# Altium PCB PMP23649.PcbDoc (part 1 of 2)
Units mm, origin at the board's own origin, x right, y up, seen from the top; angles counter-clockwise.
Board outline 75 x 70 mm, 2 copper layers (Top Layer, Bottom Layer), stack 1.575 mm thick; 49 components, 23 nets, 125 pads, 45 vias.
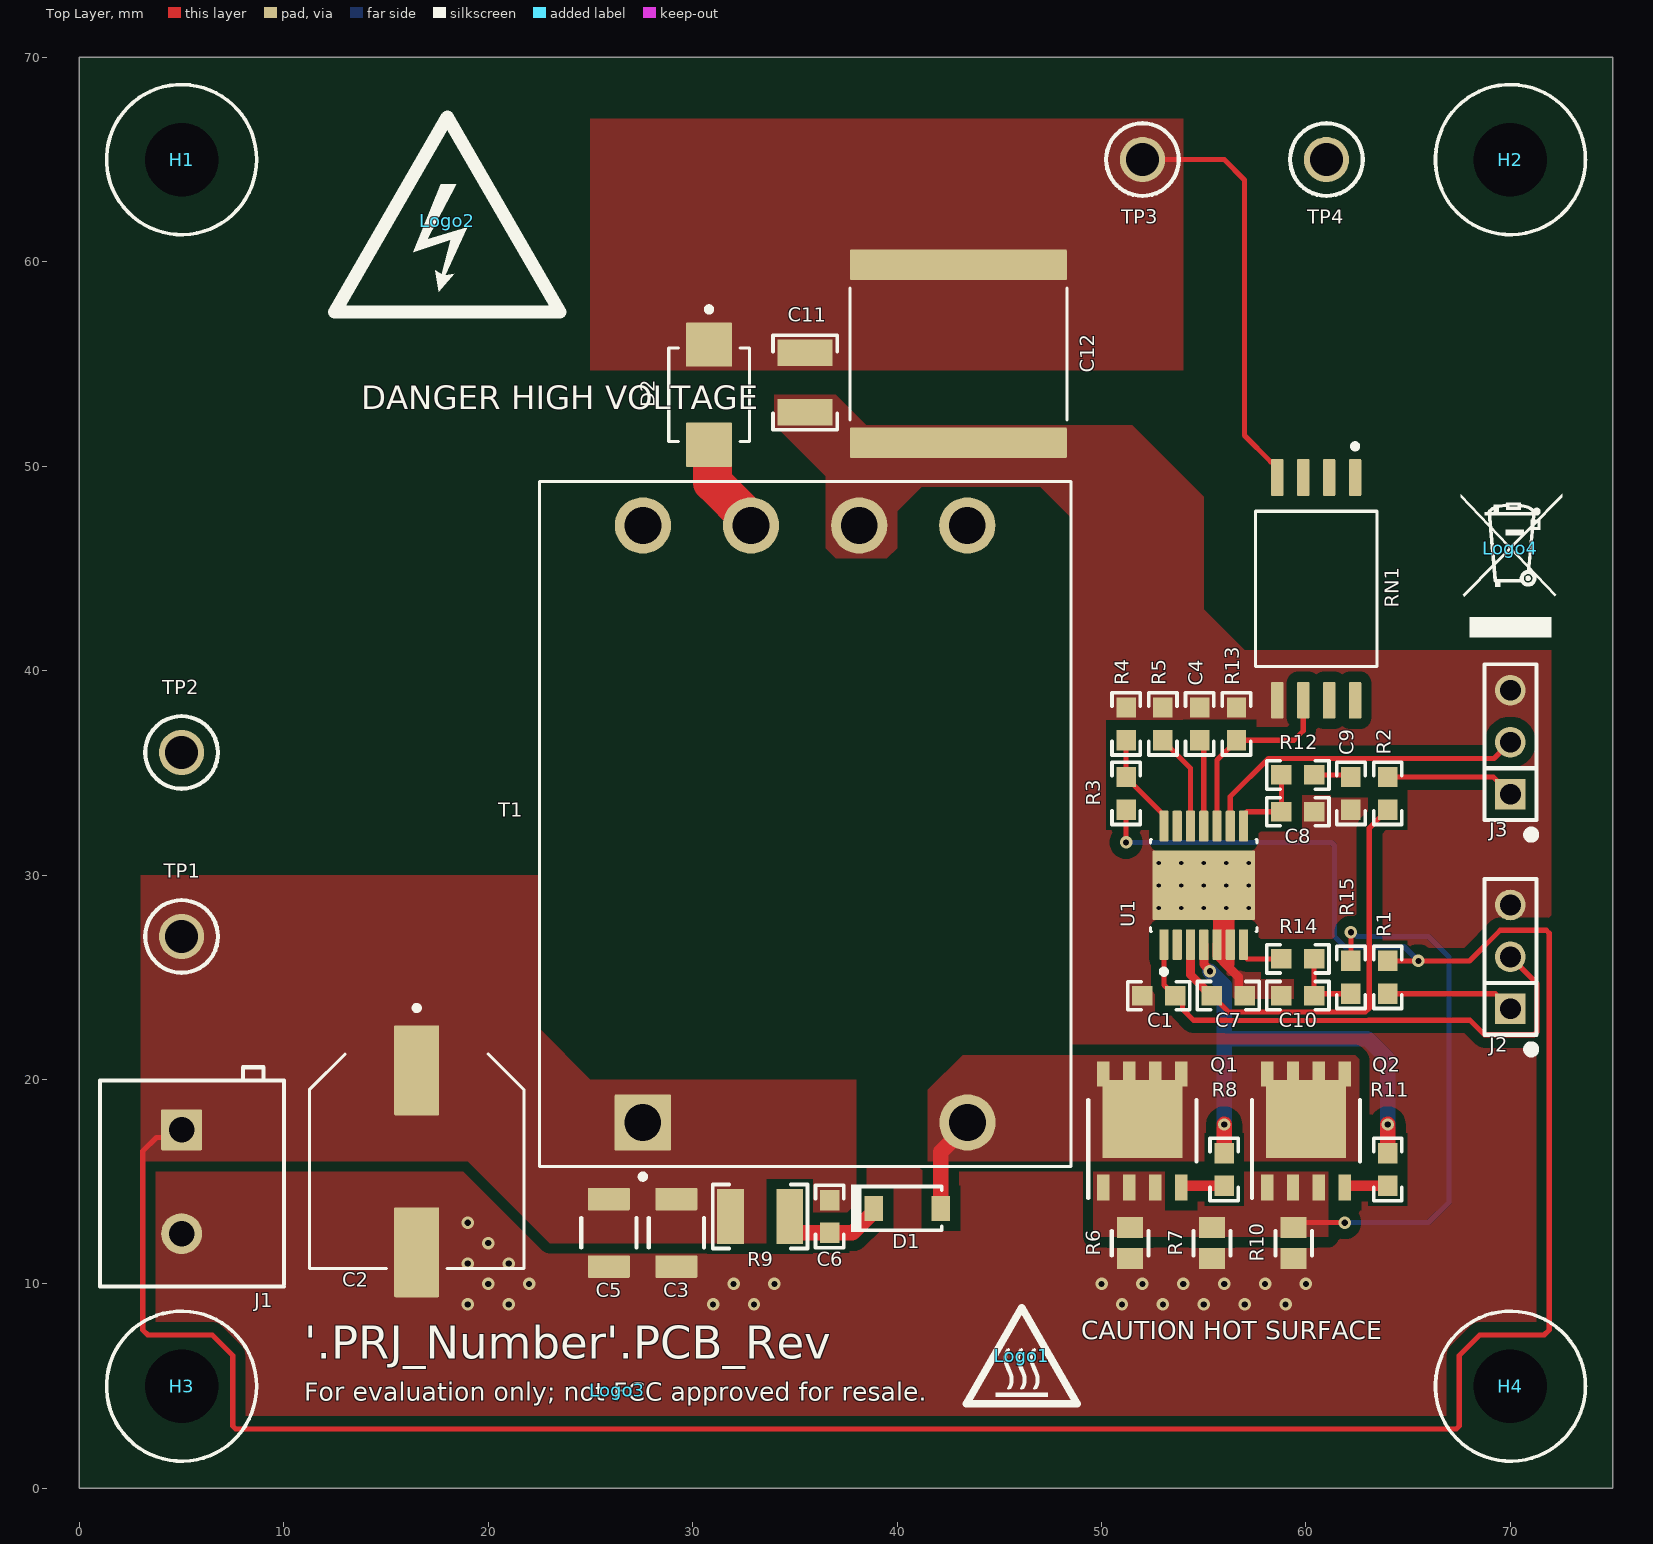
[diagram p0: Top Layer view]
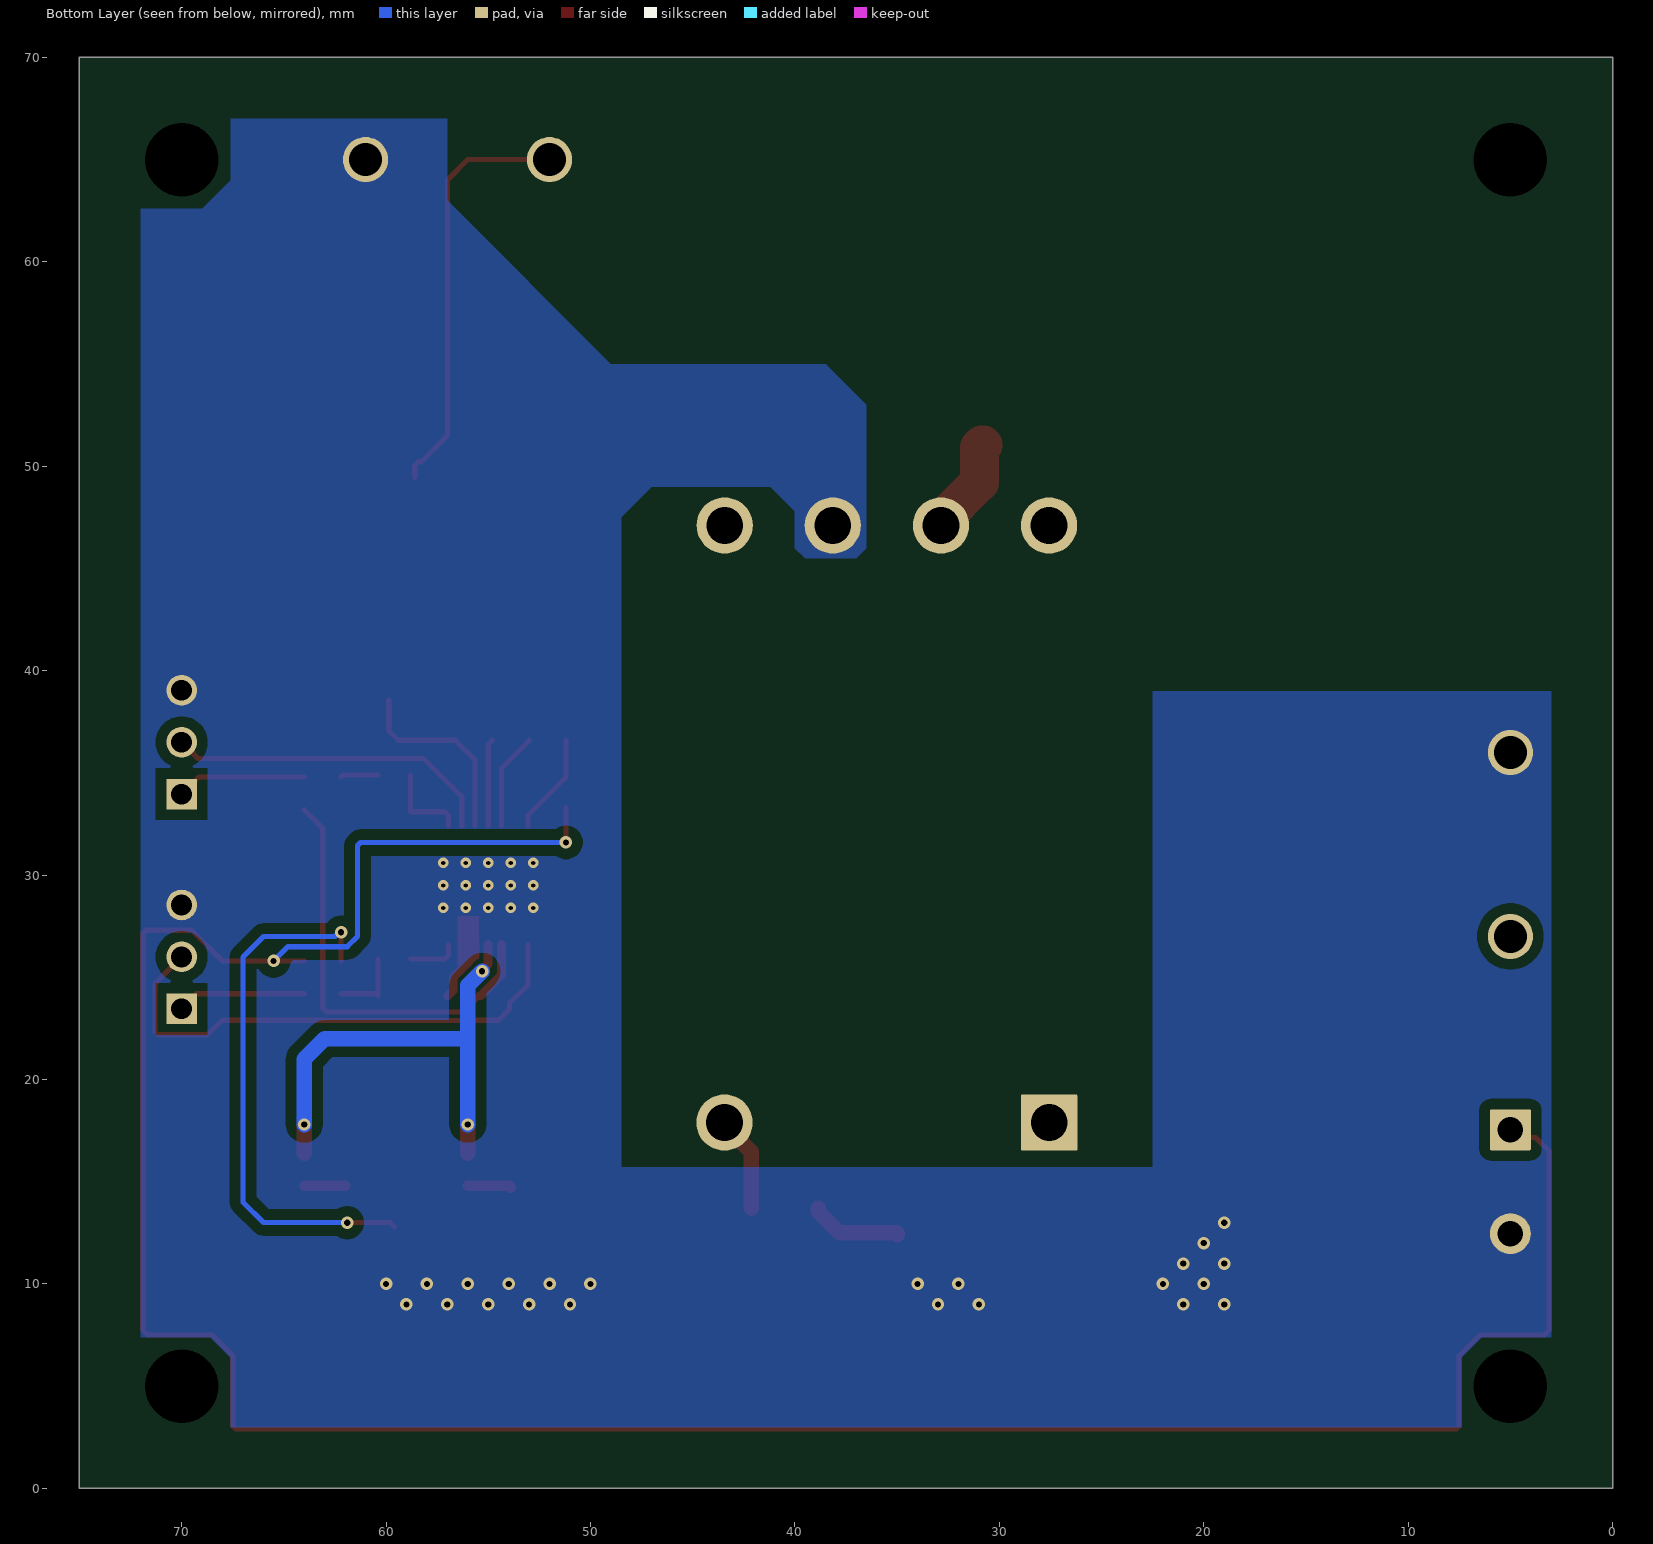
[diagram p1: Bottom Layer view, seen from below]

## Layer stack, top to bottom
Top Solder: solder mask 0.0102, Solder Resist, Dk 3.5
Top Layer: signal copper 0.0356
Dielectric1: core 1.5037, FR-4 High Tg, Dk 4.8
Bottom Layer: signal copper 0.0356
Bottom Solder: solder mask 0.0102, Solder Resist, Dk 3.5

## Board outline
0,0 0,70 75,70 75,0

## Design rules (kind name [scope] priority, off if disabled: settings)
AcuteAngle [All] p1: minimum=4.50000000000000E+0001 checktracksonly=FALSE
AssemblyTestPointUsage [All] p1: valid=2
BoardOutlineClearance BoardOutlineClearance_MountingHoles [OnCopper and InComponentClass('Mounting Holes')] p1: gap=0.635 ignorepadtopadclearanceinfootprint=FALSE
BoardOutlineClearance BoardOutlineClearance_Poly [OnCopper and InPoly] p2: gap=0.635 ignorepadtopadclearanceinfootprint=FALSE
BoardOutlineClearance [OnCopper and Not InComponentClass('Logo') and not InComponentClass('FiducialMark') and not InRegion(1000,500,4000,800)] p3: gap=0.635 ignorepadtopadclearanceinfootprint=FALSE
Clearance Clearance_2 [InNetClass('HV') vs Not InNetClass('HV')] p1: gap=1.524 ignorepadtopadclearanceinfootprint=FALSE
Clearance Clearance_1 [InNetClass('MV') vs Not InNetClass('MV')] p2: gap=0.762 ignorepadtopadclearanceinfootprint=FALSE
Clearance Clearance_Keepouts [((IsTrack Or IsArc) And Not InPoly) And IsFree and IsKeepOut vs ((IsTrack Or IsArc) And Not InPoly) And IsFree and IsKeepOut] p3: gap=0 ignorepadtopadclearanceinfootprint=FALSE
Clearance Clearance_BoardEdge_MountingHoles [OnCopper and InComponentClass('Mounting Holes') vs IsKeepOut] p4: gap=1.016 ignorepadtopadclearanceinfootprint=FALSE except(0: Arc-Hole Track-Hole SMDPad-Hole THPad-Hole Via-Hole Fill-Hole Poly-Hole Region-Hole Text-Hole)
Clearance Clearance_BoardEdge_Poly [OnCopper and InPoly vs IsKeepOut] p5: gap=1.27 ignorepadtopadclearanceinfootprint=FALSE except(0: Arc-Hole Track-Hole SMDPad-Hole THPad-Hole Via-Hole Fill-Hole Poly-Hole Region-Hole Text-Hole)
Clearance Clearance_BoardEdge [OnCopper and Not InComponentClass('Logo') and not InComponentClass('FiducialMark') and not InRegion(1000,500,4000,800) and Not IsKeepout vs IsKeepOut] p6: gap=1.27 ignorepadtopadclearanceinfootprint=FALSE
Clearance Clearance_Poly [InPolygon] p7: gap=0.508 ignorepadtopadclearanceinfootprint=FALSE except(0: Arc-Hole Track-Hole SMDPad-Hole THPad-Hole Via-Hole Fill-Hole Poly-Hole Region-Hole Text-Hole)
Clearance [All] p8: gap=0.152 ignorepadtopadclearanceinfootprint=FALSE
ComponentClearance ComponentClearance_MountingHoles_FiducialMarks [InComponentClass('Mounting Holes') vs InComponentClass('FiducialMark')] p1: gap=0.508 collisioncheckmode=3 verticalgap=0.254 showdistances=FALSE
ComponentClearance ComponentClearance_Shunt [InComponentClass('Header') vs InComponentClass('Shunt')] p2: gap=0 collisioncheckmode=3 verticalgap=0 showdistances=FALSE
ComponentClearance ComponentClearance_Logo [InComponentClass('Logo')] p3: gap=0.127 collisioncheckmode=3 verticalgap=0.254 showdistances=FALSE
ComponentClearance ComponentClearance_ScrewToNut [(HasFootprint('NY PMS 440 0025 PH')) vs (HasFootprint('Keystone_1902C'))] p4: gap=0.508 collisioncheckmode=3 verticalgap=2540 showdistances=FALSE
ComponentClearance ComponentClearance_MountingHoles [InComponentClass('Mounting Holes')] p5: gap=0.508 collisioncheckmode=3 verticalgap=0.254 showdistances=FALSE
ComponentClearance ComponentClearance_SmallPassives [HasFootprint('0201*') or HasFootprint('0402*') or HasFootprint('0508') or HasFootprint('0603*') or HasFootprint('0612') or HasFootprint('0805*') or HasFootprint('0815*') or HasFootprint('0830*') or HasFootprint('1206*') or HasFootprint('1210*') or HasFootprint('1808*') or HasFootprint('1812*') or HasFootprint('1825*') or HasFootprint('2010*') or HasFootprint('2220*') or HasFootprint('2225*') or HasFootprint('2512*') or HasFootprint('2728*') or HasFootprint('3518*') vs HasFootprint('0201*') or HasFootprint('0402*') or HasFootprint('0508') or HasFootprint('0603*') or HasFootprint('0612') or HasFootprint('0805*') or HasFootprint('0815*') or HasFootprint('0830*') or HasFootprint('1206*') or HasFootprint('1210*') or HasFootprint('1808*') or HasFootprint('1812*') or HasFootprint('1825*') or HasFootprint('2010*') or HasFootprint('2220*') or HasFootprint('2225*') or HasFootprint('2512*') or HasFootprint('2728*') or HasFootprint('3518*')] p6: gap=0.508 collisioncheckmode=3 verticalgap=0.508 showdistances=FALSE
ComponentClearance ComponentClearance_THtoSMT [IsThruComponent vs IsSMTComponent] p7: gap=0.254 collisioncheckmode=3 verticalgap=0.254 showdistances=FALSE
ComponentClearance ComponentClearance_THtoTH [IsThruComponent vs IsThruComponent] p8: gap=0.254 collisioncheckmode=3 verticalgap=0.254 showdistances=FALSE
ComponentClearance [All] p9: gap=0.254 collisioncheckmode=3 verticalgap=0.254 showdistances=FALSE
DiffPairsRouting [All] p1: maxlimit=2.54 minlimit=0.254 mostfreqgap=0.254 toplayer_minwidth=0.381 toplayer_maxwidth=0.381 toplayer_prefwidth=0.381 bottomlayer_minwidth=0.381 bottomlayer_maxwidth=0.381 bottomlayer_prefwidth=0.381 maxuncoupledlength=25.4
FabricationTestPointUsage TestPointUsage [All] p1: valid=2 allowmultiple=FALSE
FabricationTestpoint Testpoint [All] p1: side=3 testpointundercomponent=TRUE minsize=1.016 maxsize=2.54 preferedsize=1.524 minholesize=0 maxholesize=1.016 preferedholesize=0.813 testpointgrid=0.025 allowsidetop=TRUE allowsidebottom=TRUE usegrid=TRUE gridtolerance=0
FanoutControl Fanout_LCC [IsLCC] p1: bgadir=Out bgaviamode=Centered fanoutstyle=Auto fanoutdirection=Alternating viagrid=0.025 // Fanout_LCC (Default Rule)
FanoutControl Fanout_BGA [IsBGA] p2: bgadir=Out bgaviamode=Centered fanoutstyle=Auto fanoutdirection=Alternating viagrid=0.025 // Fanout_BGA (Default Rule)
FanoutControl Fanout_Default [All] p4: bgadir=Out bgaviamode=Centered fanoutstyle=Auto fanoutdirection=Alternating viagrid=0.025 // Fanout_Default (Default Rule)
FanoutControl Fanout_Small [(CompPinCount < 5)] p5: bgadir=Out bgaviamode=Centered fanoutstyle=Auto fanoutdirection=OutThenIn viagrid=0.025 // Fanout_Small (Default Rule)
Height [All] p1: minheight=0 maxheight=76.2 prefheight=12.7
HoleSize [All] p1: absolutevalues=TRUE maxlimit=6.375 minlimit=0.2 maxpercent=80.000 minpercent=20.000
MinimumAnnularRing MinimumAnnularRing_ThermalPadVias [IsVia and InAnyComponent] p1: minimumring=0.15
MinimumAnnularRing [All] p2: minimumring=0.15
MinimumSolderMaskSliver MinimumSolderMaskSliver_Logo [InComponentClass('Logo') vs InComponentClass('Logo')] p1: minsoldermaskwidth=0.018
MinimumSolderMaskSliver [All] p2: minsoldermaskwidth=0.1
PlaneConnect [All] p1: planeconnectstyle=Direct reliefexpansion=0.254 reliefentries=4 reliefconductorwidth=0.254 reliefairgap=0.254
PolygonConnect PolygonConnect_15 [All vs IsNamedPolygon('C109_2') Or  IsNamedPolygon('C107_2') Or  IsNamedPolygon('HV') Or  IsNamedPolygon('Q203_5') Or  IsNamedPolygon('C107_2') Or  IsNamedPolygon('HS') Or  IsNamedPolygon('Q201_5') Or  IsNamedPolygon('Q203_5') Or  IsNamedPolygon('C106_2') Or  IsNamedPolygon('C108_2') Or  IsNamedPolygon('Vout') Or  IsNamedPolygon('Q203_5') Or  IsNamedPolygon('C108_2') Or  IsNamedPolygon('C113_2') Or  IsNamedPolygon('Q203_5') Or  IsNamedPolygon('Q201_5') Or  IsNamedPolygon('C107_2') Or  IsNamedPolygon('C102_1') Or  IsNamedPolygon('SGND') Or  IsNamedPolygon('GND') Or  IsNamedPolygon('SGND') Or  IsNamedPolygon('GND') Or  IsNamedPolygon('IN+') Or  IsNamedPolygon('IN+') Or  IsNamedPolygon('Q201_5') Or  IsNamedPolygon('Q201_5') Or  IsNamedPolygon('SGND') Or  IsNamedPolygon('SGND') Or  IsNamedPolygon('Vout') Or  IsNamedPolygon('Vout') Or  IsNamedPolygon('IN+') Or  IsNamedPolygon('GND') Or  IsNamedPolygon('IN+') Or  IsNamedPolygon('GND')] p1: connectstyle=Direct reliefconductorwidth=0.254 reliefentries=4 polygonreliefangle="90 Angle" airgapwidth=0.254
PolygonConnect PolygonConnect_14 [All vs IsNamedPolygon('C106_2') Or  IsNamedPolygon('C107_2') Or  IsNamedPolygon('C107_2') Or  IsNamedPolygon('C107_2') Or  IsNamedPolygon('C102_1') Or  IsNamedPolygon('Q203_5') Or  IsNamedPolygon('Vout') Or  IsNamedPolygon('Q203_5') Or  IsNamedPolygon('Q203_5') Or  IsNamedPolygon('Q201_5') Or  IsNamedPolygon('C108_2') Or  IsNamedPolygon('Q203_5') Or  IsNamedPolygon('HS') Or  IsNamedPolygon('HV') Or  IsNamedPolygon('C108_2') Or  IsNamedPolygon('Q201_5') Or  IsNamedPolygon('C109_2') Or  IsNamedPolygon('Q201_5') Or  IsNamedPolygon('Q201_5') Or  IsNamedPolygon('C113_2')] p2: connectstyle=Direct reliefconductorwidth=0.254 reliefentries=4 polygonreliefangle="90 Angle" airgapwidth=0.254
PolygonConnect PolygonConnect_13 [All vs IsNamedPolygon('C102_1') Or  IsNamedPolygon('HV') Or  IsNamedPolygon('C107_2') Or  IsNamedPolygon('C109_2') Or  IsNamedPolygon('C107_2') Or  IsNamedPolygon('C108_2') Or  IsNamedPolygon('C106_2') Or  IsNamedPolygon('C108_2') Or  IsNamedPolygon('C113_2') Or  IsNamedPolygon('C107_2')] p3: connectstyle=Direct reliefconductorwidth=0.254 reliefentries=4 polygonreliefangle="90 Angle" airgapwidth=0.254
PolygonConnect PolygonConnect_12 [All vs IsNamedPolygon('C107_2') Or  IsNamedPolygon('C113_2') Or  IsNamedPolygon('C106_2') Or  IsNamedPolygon('C107_2') Or  IsNamedPolygon('C107_2') Or  IsNamedPolygon('C102_1')] p4: connectstyle=Direct reliefconductorwidth=0.254 reliefentries=4 polygonreliefangle="90 Angle" airgapwidth=0.254
PolygonConnect PolygonConnect_11 [All vs IsNamedPolygon('C106_2') Or  IsNamedPolygon('C102_1') Or  IsNamedPolygon('C107_2') Or  IsNamedPolygon('C107_2') Or  IsNamedPolygon('C107_2')] p5: connectstyle=Direct reliefconductorwidth=0.254 reliefentries=4 polygonreliefangle="90 Angle" airgapwidth=0.254
PolygonConnect PolygonConnect_10 [All vs IsNamedPolygon('C106_2')] p6: connectstyle=Direct reliefconductorwidth=0.254 reliefentries=4 polygonreliefangle="90 Angle" airgapwidth=0.254
PolygonConnect PolygonConnect_9 [All vs IsNamedPolygon('C11_1') Or  IsNamedPolygon('Vin') Or  IsNamedPolygon('Vin') Or  IsNamedPolygon('5V') Or  IsNamedPolygon('D6_2') Or  IsNamedPolygon('Q3_3') Or  IsNamedPolygon('GND2') Or  IsNamedPolygon('GND2') Or  IsNamedPolygon('GND') Or  IsNamedPolygon('Q3_4') Or  IsNamedPolygon('12V5') Or  IsNamedPolygon('GND') Or  IsNamedPolygon('12V5') Or  IsNamedPolygon('D3_1')] p7: connectstyle=Direct reliefconductorwidth=0.254 reliefentries=4 polygonreliefangle="90 Angle" airgapwidth=0.254
PolygonConnect PolygonConnect_8 [All vs IsNamedPolygon('C11_1') Or  IsNamedPolygon('Vin') Or  IsNamedPolygon('12V5') Or  IsNamedPolygon('Q3_3') Or  IsNamedPolygon('GND2') Or  IsNamedPolygon('GND2') Or  IsNamedPolygon('5V') Or  IsNamedPolygon('Q3_4') Or  IsNamedPolygon('12V5')] p8: connectstyle=Direct reliefconductorwidth=0.254 reliefentries=4 polygonreliefangle="90 Angle" airgapwidth=0.254
PolygonConnect PolygonConnect_7 [All vs IsNamedPolygon('GND2') Or  IsNamedPolygon('GND2') Or  IsNamedPolygon('5V') Or  IsNamedPolygon('12V5') Or  IsNamedPolygon('12V5') Or  IsNamedPolygon('C11_1')] p9: connectstyle=Direct reliefconductorwidth=0.254 reliefentries=4 polygonreliefangle="90 Angle" airgapwidth=0.254
PolygonConnect PolygonConnect_6 [All vs IsNamedPolygon('GND2') Or  IsNamedPolygon('SGND') Or  IsNamedPolygon('GND1') Or  IsNamedPolygon('C901_1') Or  IsNamedPolygon('SGND') Or  IsNamedPolygon('GND2') Or  IsNamedPolygon('GND1')] p10: connectstyle=Direct reliefconductorwidth=0.254 reliefentries=4 polygonreliefangle="90 Angle" airgapwidth=0.254
PolygonConnect PolygonConnect_5 [All vs IsNamedPolygon('GND1') Or  IsNamedPolygon('GND1')] p11: connectstyle=Direct reliefconductorwidth=0.254 reliefentries=4 polygonreliefangle="90 Angle" airgapwidth=0.254
PolygonConnect PolygonConnect_4 [All vs IsNamedPolygon('C21_1') Or  IsNamedPolygon('C5_1') Or  IsNamedPolygon('C12_2') Or  IsNamedPolygon('C2_2') Or  IsNamedPolygon('C13_1') Or  IsNamedPolygon('C28_1') Or  IsNamedPolygon('C6_1') Or  IsNamedPolygon('GND') Or  IsNamedPolygon('GND2') Or  IsNamedPolygon('C14_1') Or  IsNamedPolygon('C13_1') Or  IsNamedPolygon('Q1_3') Or  IsNamedPolygon('C14_1') Or  IsNamedPolygon('C5_1') Or  IsNamedPolygon('GND2') Or  IsNamedPolygon('C28_1') Or  IsNamedPolygon('D5_2') Or  IsNamedPolygon('D6_2') Or  IsNamedPolygon('D2_1') Or  IsNamedPolygon('C12_2') Or  IsNamedPolygon('D2_1') Or  IsNamedPolygon('C4_1') Or  IsNamedPolygon('C4_1') Or  IsNamedPolygon('C2_2') Or  IsNamedPolygon('GND') Or  IsNamedPolygon('C33_1') Or  IsNamedPolygon('C9_1')] p12: connectstyle=Direct reliefconductorwidth=0.254 reliefentries=4 polygonreliefangle="90 Angle" airgapwidth=0.254
PolygonConnect PolygonConnect_3 [All vs IsNamedPolygon('C28_1') Or  IsNamedPolygon('C12_2') Or  IsNamedPolygon('C28_1') Or  IsNamedPolygon('C9_1') Or  IsNamedPolygon('D5_2') Or  IsNamedPolygon('C12_2') Or  IsNamedPolygon('C2_2') Or  IsNamedPolygon('C14_1') Or  IsNamedPolygon('C4_1') Or  IsNamedPolygon('C14_1') Or  IsNamedPolygon('D6_2') Or  IsNamedPolygon('GND2') Or  IsNamedPolygon('Q1_3') Or  IsNamedPolygon('C5_1') Or  IsNamedPolygon('D2_1') Or  IsNamedPolygon('C4_1') Or  IsNamedPolygon('C13_1') Or  IsNamedPolygon('C5_1') Or  IsNamedPolygon('C13_1') Or  IsNamedPolygon('C33_1') Or  IsNamedPolygon('D2_1') Or  IsNamedPolygon('GND') Or  IsNamedPolygon('GND') Or  IsNamedPolygon('GND2') Or  IsNamedPolygon('C2_2') Or  IsNamedPolygon('C6_1') Or  IsNamedPolygon('C21_1')] p13: connectstyle=Direct reliefconductorwidth=0.254 reliefentries=4 polygonreliefangle="90 Angle" airgapwidth=0.254
PolygonConnect PolygonConnect_2 [All vs IsNamedPolygon('C21_1') Or  IsNamedPolygon('C4_1') Or  IsNamedPolygon('D5_2') Or  IsNamedPolygon('C5_1') Or  IsNamedPolygon('C14_1') Or  IsNamedPolygon('C13_1') Or  IsNamedPolygon('C4_1') Or  IsNamedPolygon('C33_1') Or  IsNamedPolygon('C12_2') Or  IsNamedPolygon('D2_1') Or  IsNamedPolygon('C2_2') Or  IsNamedPolygon('C28_1') Or  IsNamedPolygon('C12_2') Or  IsNamedPolygon('D2_1') Or  IsNamedPolygon('C5_1') Or  IsNamedPolygon('Q1_3') Or  IsNamedPolygon('GND') Or  IsNamedPolygon('D6_2') Or  IsNamedPolygon('C6_1') Or  IsNamedPolygon('C2_2') Or  IsNamedPolygon('C14_1') Or  IsNamedPolygon('C28_1') Or  IsNamedPolygon('C13_1') Or  IsNamedPolygon('C9_1') Or  IsNamedPolygon('GND')] p14: connectstyle=Direct reliefconductorwidth=0.254 reliefentries=4 polygonreliefangle="90 Angle" airgapwidth=0.254
PolygonConnect PolygonConnect_1 [All vs IsNamedPolygon('C28_1') Or  IsNamedPolygon('D5_2') Or  IsNamedPolygon('C5_1') Or  IsNamedPolygon('C5_1') Or  IsNamedPolygon('D2_1') Or  IsNamedPolygon('C21_1') Or  IsNamedPolygon('C9_1') Or  IsNamedPolygon('C4_1') Or  IsNamedPolygon('C14_1') Or  IsNamedPolygon('C28_1') Or  IsNamedPolygon('C6_1') Or  IsNamedPolygon('C12_2') Or  IsNamedPolygon('C33_1') Or  IsNamedPolygon('C4_1') Or  IsNamedPolygon('C13_1') Or  IsNamedPolygon('C12_2') Or  IsNamedPolygon('D6_2') Or  IsNamedPolygon('C2_2') Or  IsNamedPolygon('C14_1') Or  IsNamedPolygon('D2_1') Or  IsNamedPolygon('C2_2') Or  IsNamedPolygon('C13_1')] p15: connectstyle=Direct reliefconductorwidth=0.254 reliefentries=4 polygonreliefangle="90 Angle" airgapwidth=0.254
PolygonConnect [All] p16: connectstyle=Direct reliefconductorwidth=0.254 reliefentries=4 polygonreliefangle="90 Angle" airgapwidth=0.254
RoutingVias ThermalPadVias [IsVia and InAnyComponent] p1: holewidth=0.2 width=0.5 viastyle="Through Hole" minholewidth=0.2 minwidth=0.5 maxholewidth=0.33 maxwidth=0.6
RoutingVias [All] p2: holewidth=0.406 width=0.864 viastyle="Through Hole" minholewidth=0.15 minwidth=0.25 maxholewidth=1.016 maxwidth=1.651
SilkToBoardRegionClearance [Not ((IsComment or IsDesignator) And (Hide <> 'False')) and not InRegion(1000,500,4000,800)] p1:
SilkToSilkClearance SilkToSilkClearance_Pb-FreeLogo [(HasFootprint('Pb-Free_Overlay_Medium') OR HasFootprint('Pb-Free_Overlay_Small')) vs (HasFootprint('Pb-Free_Overlay_Medium') OR HasFootprint('Pb-Free_Overlay_Small'))] p1: silktosilkclearance=0
SilkToSilkClearance [All] p2: silktosilkclearance=0.102
SilkToSolderMaskClearance SilkToComponentPadClearance [IsPad and InAnycomponent] p1: minsilkscreentomaskgap=0.127 clearancetoexposedcopper=TRUE
SilkToSolderMaskClearance "Silk to Solder Mask Opening" [All] p2: minsilkscreentomaskgap=0.102 clearancetoexposedcopper=FALSE
SolderMaskExpansion [All] p1: expansion=0.05 istentingtop=FALSE
SupplyNets "Schematic Supply Nets_8" [InNet('HV')] p1: voltage=0.000
SupplyNets "Schematic Supply Nets_7" [InNet('GND')] p2: voltage=0.000
Width [All] p1: maxlimit=2.54 minlimit=0.152 preferedwidth=0.254 checkconnectedcopper=TRUE
14 further rules are at their usual default settings.

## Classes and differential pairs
component class Header: J2 J3

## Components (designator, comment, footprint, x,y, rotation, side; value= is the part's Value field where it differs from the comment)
C1 "GRM188R72A104KA35D" 0603 52.8,24.1 r180 top value=0.1uF
C2 "HHXD630ARA101MJA0G" FP-HHXD630ARA101MJA0G_SMT_CAP_10MM3_10MM3-MFG 16.5,16 r90 top value=100µF
C3 "GRM32EC72A106KE05L" FP-GRM32EC72A106KE05L_1210-MFG 29.2,12.5 r90 top
C4 "GRM188R61C225KAAD" 0603 54.8,37.4 r90 top value=2.2uF
C5 "GRM32EC72A106KE05L" FP-GRM32EC72A106KE05L_1210-MFG 25.9,12.5 r90 top
C6 "GRM188R72A392KA01D" 0603 36.7,13.3 r270 top value=3900pF
C7 "GRM188R61C225KAAD" 0603 56.2,24.1 r0 top value=2.2uF
C8 "GRM188R71H221KA01D" 0603 59.6,33.1 r0 top value=220pF
C9 "GRM188R71H223KA01D" 0603 62.2,34 r270 top value=0.022uF
C10 "GRM1885C1H330JA01D" 0603 59.6,24.1 r0 top value=33pF
C11 "C1210C472KGRACTU" 1210_230 35.5,54.1 r270 top value=4700pF
C12 "CKC33C603KGGLCAUTO" FP-CKC33C603KGGLCAUTO_3640-MFG 43,55.5 r90 top value=60nF
D1 "1N4148WFL-G3-08" SOD-123FL 40.5,13.7 r0 top value=100V
D2 "GAP3SLT33-214" FP-GAP3SLT33-214_DO-214AA-MFG 30.8,53.5 r270 top
H1 "4820" KEYSTONE_4820 5,65 r0 top
H2 "4820" KEYSTONE_4820 70,65 r0 top
H3 "4820" KEYSTONE_4820 5,5 r0 top
H4 "4820" KEYSTONE_4820 70,5 r0 top
J1 "ED120/2DS" On-Shore_ED120_2DS 5,15 r270 top
J2 "PEC03SAAN" CONN_PEC03SAAN 70,26 r90 top
J3 "PEC03SAAN" CONN_PEC03SAAN 70,36.5 r90 top
Logo1 "CAUTION HOT SURFACE" IEC_HotSurface_Small 46.1,6.5 r0 top (schematic designator LOGO1)
Logo2 "DANGER HIGH VOLTAGE" IEC_HighVoltage_Medium 18,62 r0 top (schematic designator LOGO2)
Logo3 "FCC disclaimer" FCC_disclaimer 26.3,4.8 r0 top
Logo4 "WEEE logo" WEEE_Minimum 70,46 r0 top
Q1 "SI7190ADP-T1-GE3" PowerPAK_SO-8 52,17.5 r90 top value=250V
Q2 "SI7190ADP-T1-GE3" PowerPAK_SO-8 60,17.5 r90 top value=250V
R1 "CRCW060310R0JNEA" 0603 64,25 r270 top value=10
R2 "CRCW060310R0JNEA" 0603 64,34 r270 top value=10
R3 "CRCW0603100KFKEA" 0603 51.2,34 r270 top value=100k
R4 "CRCW06031K69FKEA" 0603 51.2,37.4 r270 top value=1.69k
R5 "CRCW060378K7FKEA" 0603 53,37.4 r270 top value=78.7k
R6 "WSLP0805R0300FEB" WSLP0805 51.4,12 r90 top value=0.03
R7 "WSLP0805R0300FEB" WSLP0805 55.4,12 r90 top value=0.03
R8 "CRCW06030000Z0EA" 0603 56,15.6 r90 top value=0
R9 "RC1210JR-0710KL" 1210 33.3,13.3 r180 top value=10k
R10 "WSLP0805R0300FEB" WSLP0805 59.4,12 r90 top value=0.03
R11 "CRCW06030000Z0EA" 0603 64,15.6 r90 top value=0
R12 "CRCW060315K0FKEA" 0603 59.6,34.9 r180 top value=15.0k
R13 "CRCW060327K4FKEA" 0603 56.6,37.4 r270 top value=27.4k
R14 "CRCW0603100RFKEA" 0603 59.6,25.9 r0 top value=100
R15 "CRCW06031K00FKEA" 0603 62.2,25 r270 top value=1.00k
RN1 "RES60A500QDWVRQ1" DWV0008A-MFG 60.5,44 r270 top
T1 "AF2556-DL" FP-AF2556-DL_PTH_XFRMR_33MM5_26MM0-MFG 35.5,32.5 r90 top
TP1 "5010" Keystone5010 5,27 r90 top
TP2 "5011" Keystone5011 5,36 r90 top
TP3 "5010" Keystone5010 52,65 r0 top
TP4 "5011" Keystone5011 61,65 r0 top
U1 "LM5156HPWPR" PWP0014H-MFG 55,29.5 r90 top

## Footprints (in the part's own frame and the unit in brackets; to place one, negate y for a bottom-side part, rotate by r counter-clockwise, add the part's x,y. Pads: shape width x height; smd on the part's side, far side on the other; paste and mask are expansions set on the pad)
0603 [mm] "0603 from SM-752 data"
  rect 1x0.95 smd: 1(-0.8,0) 2(0.8,0)
  silkscreen extent -1.52,-0.69 1.52,0.69, body extent -0.87,-0.47 0.87,0.47, height 1
1210 [mm] "1210 from SM-752 data"
  rect 1.3x2.7 smd: 1(-1.45,0) 2(1.45,0)
  silkscreen extent -2.32,-1.57 2.32,1.57, body extent -1.7,-1.35 1.7,1.35, height 1.35
1210_230 [mm] "1210"
  rect 1.3x2.7 smd: 1(-1.45,0) 2(1.45,0)
  silkscreen extent -2.32,-1.57 2.32,1.57, body extent -1.7,-1.35 1.7,1.35, height 2.3
CONN_PEC03SAAN [mm] "SULLINS"
  rect 1.5x1.5 hole 1.016: 1(-2.54,0)
  round 1.5 hole 1.016: 2(0,0) 3(2.54,0)
  silkscreen extent -4.72,-1.27 3.81,1.27, body extent -3.84,-1.3 3.84,1.3, height 8.38
DWV0008A-MFG [mm]
  rrect17% 1.8x0.6 smd paste+0 mask+0: 1(-5.45,1.905) 2(-5.45,0.635) 3(-5.45,-0.635) 4(-5.45,-1.905) 5(5.45,-1.905) 6(5.45,-0.635) 7(5.45,0.635) 8(5.45,1.905)
  silkscreen extent -7.1,-2.98 3.8,2.98, body extent -6.45,-3.22 6.45,3.22, height 0.25
FCC_disclaimer [mm]
FP-AF2556-DL_PTH_XFRMR_33MM5_26MM0-MFG [mm] "Recommended Land Pattern"
  rrect4% 2.75x2.75 hole 1.8 paste-2539.97 mask+0: 1(-14.605,7.94)
  round 2.75 hole 1.8 paste-2539.97 mask+0: 3(-14.605,-7.94) 4(14.605,-7.935) 5(14.605,-2.645) 6(14.605,2.645) 7(14.605,7.935)
  silkscreen extent -17.37,-13 16.75,13, body extent -16.85,-13.1 16.85,13.1, height 0.25
FP-CKC33C603KGGLCAUTO_3640-MFG [mm] "Recommended Land Pattern"
  rrect7% 1.5x10.6 smd paste+0 mask+0: 1(-4.35,0) 2(4.35,0)
  silkscreen extent -3.22,-5.3 3.22,5.3, body extent -5.35,-5.55 5.35,5.55, height 0.25
FP-GAP3SLT33-214_DO-214AA-MFG [mm] "Recommended Land Pattern"
  rrect5% 2.16x2.26 smd paste+0 mask+0: 1(-2.45,0) 2(2.45,0)
  silkscreen extent -4.3,-1.97 2.28,1.97, body extent -3.63,-2.07 3.63,2.07, height 0.25
FP-GRM32EC72A106KE05L_1210-MFG [mm]
  rrect9% 1.1x2.05 smd paste+0 mask+0: 1(-1.65,0) 2(1.65,0)
  silkscreen extent -0.72,-1.35 0.72,1.35, body extent -2.3,-1.45 2.3,1.45, height 0.25
FP-HHXD630ARA101MJA0G_SMT_CAP_10MM3_10MM3-MFG [mm]
  rrect5% 4.4x2.2 smd paste+0 mask+0: 1(-4.45,0) 2(4.45,0)
  silkscreen extent -5.25,-5.25 7.62,5.25, body extent -6.9,-5.5 6.9,5.5, height 0.25
IEC_HighVoltage_Medium [mm]
  silkscreen extent -5.51,-4.46 5.51,5.09
IEC_HotSurface_Small [mm]
  silkscreen extent -2.72,-2.36 2.72,2.35
Keystone5010 [mil] "Keystone Multipurpose loops"
  round 87 hole 63: 1(0,0)
  silkscreen extent -70,-70 70,70, body extent -63,-63 63,62, height 319
Keystone5011 [mil] "Keystone Multipurpose loops"
  round 87 hole 63: 1(0,0)
  silkscreen extent -70,-70 70,70, body extent -63,-63 63,62, height 319
KEYSTONE_4820 [mm] "HEX NYLON STANDOFF 6-32, M-F 1\""
  round 0.025 on Mech3: 0(0,0)
  round 1 hole 3.6 unplated: MH(0,0)
  silkscreen extent -3.67,-3.67 3.67,3.67, body extent -3.67,-3.17 3.67,3.18, height 25.42
On-Shore_ED120_2DS [mm] "ONSHORE"
  rrect5% 2x2 hole 1.25: 1(-2.54,0)
  round 2 hole 1.25: 2(2.54,0)
  silkscreen extent -5.6,-4 5.12,5, body extent -5.78,-4 5.08,5, height 13
PowerPAK_SO-8 [mil] "Vishay PowerPAK SO-8, Body 5.3x6.0mm (max), Pitch 1.27mm, IPC Medium Density"
  rect 50x24 smd mask+2.99: 1(-109.5,75) 2(-109.5,25) 3(-109.5,-25) 4(-109.5,-75)
  rect 48x24 smd mask+2.99: 5(109.5,-75) 8(109.5,75)
  rect 48x24 smd paste-12 mask+2.99: 6(109.5,-25) 7(109.5,25)
  rect 150x154 smd paste-75 mask+2.99: 9(22.5,0)
  silkscreen extent -130,-104 59,104, body extent -121,-102 121,102, height 43
PWP0014H-MFG [mm]
  rrect22% 1.5x0.45 smd paste+0 mask+0: 1(-2.9,1.95) 2(-2.9,1.3) 3(-2.9,0.65) 4(-2.9,0) 5(-2.9,-0.65) 6(-2.9,-1.3) 7(-2.9,-1.95) 8(2.9,-1.95) 9(2.9,-1.3) 10(2.9,-0.65) 11(2.9,0) 12(2.9,0.65) 13(2.9,1.3) 14(2.9,1.95)
  rrect3% 3.4x5 smd paste-1000 mask-1000: 15(0,0)
  silkscreen extent -4.35,-2.6 2.25,2.6, body extent -3.75,-2.8 3.75,2.8, height 0.25
SOD-123FL [mm] "Copied from SOD-123"
  rect 0.915x1.22 smd: 1(-1.637,0) 2(1.637,0)
  silkscreen extent -2.74,-1.16 1.68,1.16, body extent -1.9,-0.9 1.9,0.9, height 1
WEEE_Minimum [mm] "WEEElie bin"
  silkscreen extent -2.42,-4.38 2.52,2.65
WSLP0805 [mm] "Vishay"
  rect 1.02x1.27 smd: 1(-0.76,0) 2(0.76,0)
  silkscreen extent -0.6,-0.9 0.6,0.9, body extent -1.14,-0.76 1.14,0.76, height 0.64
